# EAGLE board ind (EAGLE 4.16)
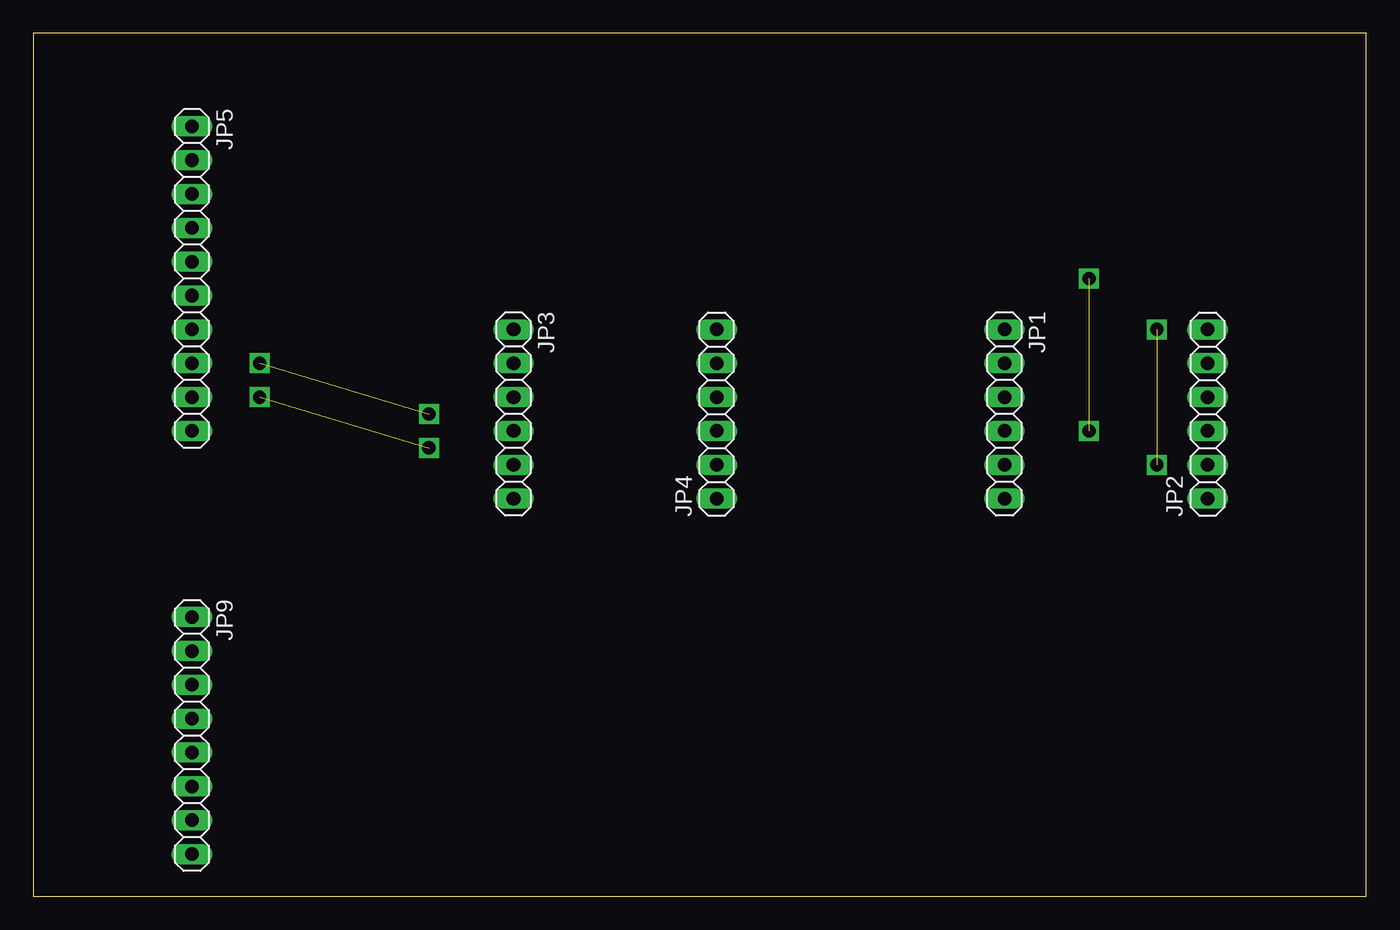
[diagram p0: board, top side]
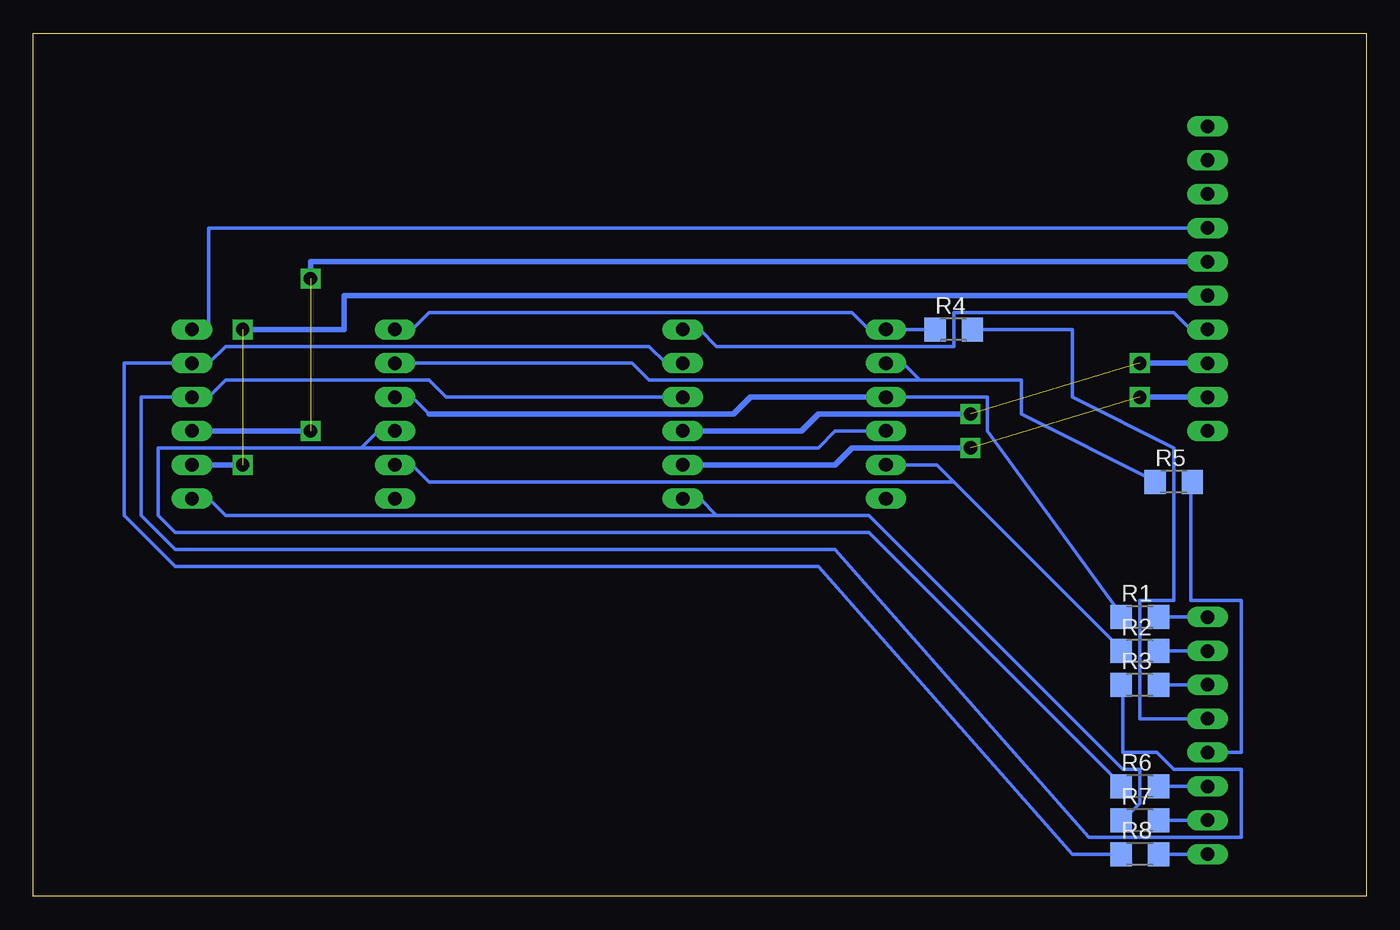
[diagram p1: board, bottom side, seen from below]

Size 100 x 64.76 mm. Coordinates in mm from the lower left corner, seen from the top.
Outline: 0,0 100,0 100,64.76 0,64.76 0,0
Copper layers (1*16): Top 0.035mm / dielectric 1.5mm / Bottom 0.035mm
Design rules "default": minimum track width 10mil, minimum drill 24mil, track to track 8mil, track to pad 8mil, pad to pad 8mil, via to via 8mil, smd to smd 8mil, copper to edge 40mil, drill to drill 8mil, minimum pad ring 10mil, minimum via ring 8mil, stop-mask expansion 4mil, vias tented up to drill 0mil, thermal gap 10mil

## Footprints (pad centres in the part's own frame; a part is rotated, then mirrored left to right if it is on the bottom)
1X06 = drill 1.016 long: 1 -6.35,0; 2 -3.81,0; 3 -1.27,0; 4 1.27,0; 5 3.81,0; 6 6.35,0
1X10 = drill 1.016 long: 1 -11.43,0; 2 -8.89,0; 3 -6.35,0; 4 -3.81,0; 5 -1.27,0; 6 1.27,0; 7 3.81,0; 8 6.35,0; 9 8.89,0; 10 11.43,0
1X08 = drill 1.016 long: 1 -8.89,0; 2 -6.35,0; 3 -3.81,0; 4 -1.27,0; 5 1.27,0; 6 3.81,0; 7 6.35,0; 8 8.89,0
R1206 = smd 1.6 x 1.8: 1 -1.4,0; 2 1.4,0

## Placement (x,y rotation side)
JP1  [1X06]  72.86,36.19 270 top
JP2  [1X06]  88.1,36.19 90 top
JP3  [1X06]  36.03,36.19 270 top
JP4  [1X06]  51.27,36.19 90 top
JP5  [1X10]  11.9,46.35 270 top
JP9  [1X08]  11.9,12.06 270 top
R1  240  [R1206]  16.98,20.95 0 bottom
R2  240  [R1206]  16.98,18.41 0 bottom
R3  240  [R1206]  16.98,15.87 0 bottom
R4  240  [R1206]  30.95,42.54 0 bottom
R5  240  [R1206]  14.44,31.11 0 bottom
R6  240  [R1206]  16.98,8.25 0 bottom
R7  240  [R1206]  16.98,5.71 0 bottom
R8  240  [R1206]  16.98,3.17 0 bottom

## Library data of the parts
JP1-JP5 JP9 = pinhead
R1-R8 = rcl

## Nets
N$1: JP4.2 JP5.9
N$10: JP2.5 JP4.5 R8.1
N$12: JP2.1 JP4.1 R7.1
N$13: JP1.4 JP3.4 R6.1
N$14: JP1.2 JP3.2 R5.1
N$15: JP9.1 R1.2
N$16: JP9.2 R2.2
N$17: JP9.3 R3.2
N$18: JP9.4 R4.2
N$19: JP9.5 R5.2
N$20: JP9.6 R6.2
N$21: JP9.7 R7.2
N$22: JP9.8 R8.2
N$23: JP2.6 JP5.4
N$24: JP2.3 JP5.5
N$25: JP2.2 JP5.6
N$26: JP4.6 JP5.7
N$27: JP4.3 JP5.8
N$28: JP1.1 JP3.1 R4.1
N$29: JP2.4 JP4.4 R3.1
N$30: JP1.5 JP3.5 R2.1
N$31: JP1.3 JP3.3 R1.1

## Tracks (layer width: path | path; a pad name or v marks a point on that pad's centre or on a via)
N$1  (1 unrouted)
  Bottom 0.406: JP4.2 39.84,32.38 38.57,33.65 29.68,33.65 | JP5.9 16.98,37.46
N$10
  Bottom 0.254: 18.25,3.17 R8.1 22.06,3.17 41.11,24.76 89.37,24.76 93.18,28.57 93.18,40 JP2.5 86.83,40 85.56,41.27 53.81,41.27 52.54,40 JP4.5
N$12
  Bottom 0.254: 48.73,28.57 37.3,28.57 18.25,9.52 16.98,9.52 16.98,6.98 18.25,5.71 R7.1 | 48.73,28.57 50,29.84 JP4.1 | 48.73,28.57 85.56,28.57 86.83,29.84 JP2.1
N$13
  Bottom 0.254: 75.4,33.65 90.64,33.65 90.64,28.57 89.37,27.3 37.3,27.3 18.25,8.25 R6.1 | 75.4,33.65 74.13,34.92 JP1.4 | 75.4,33.65 41.11,33.65 39.84,34.92 JP3.4
N$14
  Bottom 0.254: 33.49,38.73 34.76,40 JP3.2 | 33.49,38.73 25.87,38.73 25.87,36.19 15.71,31.11 R5.1 | 33.49,38.73 53.81,38.73 55.08,40 JP1.2
N$15
  Bottom 0.254: 15.71,20.95 R1.2 JP9.1
N$16
  Bottom 0.254: 15.71,18.41 R2.2 JP9.2
N$17
  Bottom 0.254: 15.71,15.87 R3.2 JP9.3
N$18
  Bottom 0.254: 29.68,42.54 R4.2 22.06,42.54 22.06,37.46 14.44,33.65 14.44,22.22 16.98,22.22 16.98,13.33 JP9.4
N$19
  Bottom 0.254: R5.2 13.17,31.11 13.17,22.22 9.36,22.22 9.36,10.79 JP9.5
N$20
  Bottom 0.254: 15.71,8.25 R6.2 JP9.6
N$21
  Bottom 0.254: 15.71,5.71 R7.2 JP9.7
N$22
  Bottom 0.254: 15.71,3.17 R8.2 JP9.8
N$23
  Bottom 0.254: JP2.6 86.83,42.54 86.83,50.16 JP5.4
N$24  (1 unrouted)
  Bottom 0.406: 79.21,34.92 JP2.3 | JP5.5 79.21,47.62 79.21,46.35
N$25  (1 unrouted)
  Bottom 0.406: 84.29,32.38 JP2.2 | JP5.6 76.67,45.08 76.67,42.54 84.29,42.54
N$26
  Bottom 0.254: JP5.7 13.17,42.54 14.44,43.81 30.95,43.81 30.95,41.27 48.73,41.27 50,42.54 JP4.6
N$27  (1 unrouted)
  Bottom 0.406: JP4.3 42.38,34.92 41.11,36.19 29.68,36.19 | JP5.8 16.98,40
N$28
  Bottom 0.254: 32.22,42.54 R4.1 JP3.1 37.3,42.54 38.57,43.81 70.32,43.81 71.59,42.54 JP1.1
N$29
  Bottom 0.254: R3.1 18.25,15.87 18.25,10.79 15.71,10.79 14.44,9.52 9.36,9.52 9.36,4.44 20.79,4.44 39.84,26.03 89.37,26.03 91.91,28.57 91.91,37.46 JP2.4 86.83,37.46 85.56,38.73 70.32,38.73 69.05,37.46 JP4.4
N$30
  Bottom 0.254: 30.95,31.11 32.22,32.38 JP3.5 | 30.95,31.11 18.25,18.41 R2.1 | 30.95,31.11 70.32,31.11 71.59,32.38 JP1.5
N$31
  Bottom 0.254: R1.1 18.25,20.95 28.41,34.92 28.41,37.46 JP3.3 | 70.32,36.19 71.59,37.46 JP1.3
  Bottom 0.406: 70.32,36.19 47.46,36.19 46.19,37.46 JP3.3
N$32  (via drill 1)
  other vias: 84.29,32.38
N$33  (via drill 1)
  other vias: 79.21,34.92
N$34  (via drill 1)
  other vias: 84.29,42.54
N$35  (via drill 1)
  other vias: 79.21,46.35
N$36  (via drill 1)
  other vias: 16.98,40
N$37  (via drill 1)
  other vias: 16.98,37.46
N$38  (via drill 1)
  other vias: 29.68,33.65
N$39  (via drill 1)
  other vias: 29.68,36.19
